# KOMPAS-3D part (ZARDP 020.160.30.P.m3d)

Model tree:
1. Плоскость XY
2. Плоскость ZX
3. Плоскость ZY
4. Ось X
5. Ось Y
6. Ось Z
7. Начало координат
8. Смещенная плоскость:2
     Расстояние = 60
9. Смещенная плоскость:3
     Расстояние = 102
10. Смещенная плоскость:4
     Расстояние = 102
11. Булева операция:1
12. Булева операция:2
13. Булева операция:3
14. Булева операция:4
15. Булева операция:5
16. Булева операция:6
